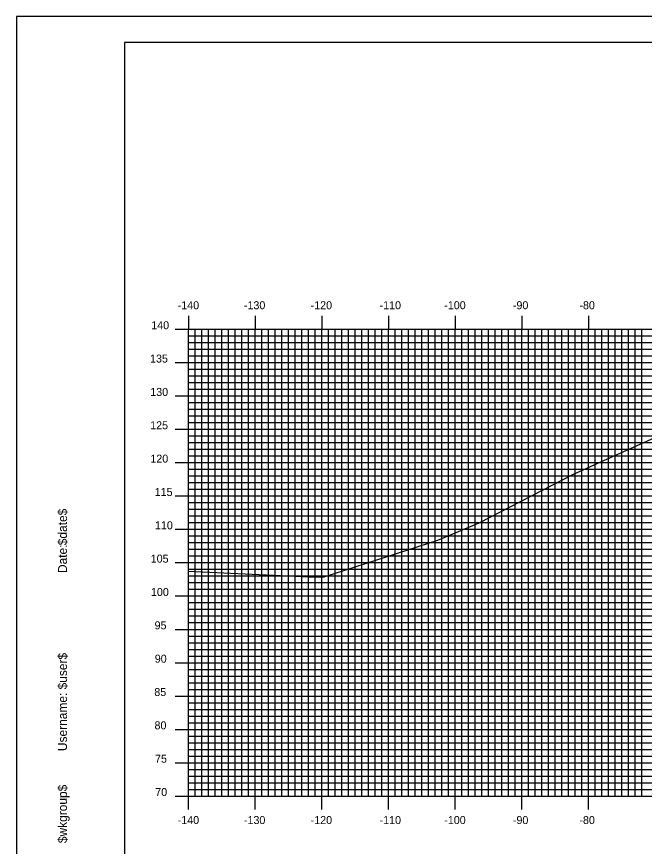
# Model space of a CAD drawing. Extents: x 859078 to 859421, y 364765 to 364985.
# Drawn here: x 859077.6 to 859171.7, y 364860.7 to 364985.2 of the extents above; entities that cross this region are included whole.
import ezdxf

# ---------------------------------------------------------------- set-up
doc = ezdxf.new("R2010")
doc.units = 0
for name, color, linetype in [('BORDER', 7, 'Continuous'), ('H_V ANNOTATION', 7, 'Continuous'), ('MAJOR', 7, 'Continuous'), ('MINOR', 7, 'Continuous'), ('PLOT BOUNDARY', 7, 'Continuous'), ('S_Roadway_Centerline', 7, 'Continuous')]:
    doc.layers.add(name, color=color, linetype=linetype)

msp = doc.modelspace()

# ---------------------------------------------------------------- linework, layer by layer
at = {"layer": 'BORDER'}
msp.add_lwpolyline([(859093.76, 364771.3), (859413.76, 364771.3), (859413.76, 364981.3), (859093.76, 364981.3)], close=True, dxfattribs=at)
at = {"layer": 'MAJOR'}
for p, q in [((859103.36, 364940.31), (859103.36, 364938.3)), ((859113.36, 364940.31), (859113.36, 364938.3)), ((859123.36, 364940.31), (859123.36, 364938.3)), ((859133.36, 364940.31), (859133.36, 364938.3)), ((859143.36, 364940.31), (859143.36, 364938.3)), ((859153.36, 364940.31), (859153.36, 364938.3)), ((859163.36, 364940.31), (859163.36, 364938.3)), ((859101.36, 364938.3), (859103.36, 364938.3)), ((859103.36, 364938.3), (859383.36, 364938.3)), ((859103.36, 364868.3), (859103.36, 364938.3)), ((859103.36, 364868.3), (859103.36, 364938.3)), ((859103.36, 364938.3), (859383.36, 364938.3)), ((859113.36, 364868.3), (859113.36, 364938.3)), ((859123.36, 364868.3), (859123.36, 364938.3)), ((859133.36, 364868.3), (859133.36, 364938.3)), ((859143.36, 364868.3), (859143.36, 364938.3)), ((859153.36, 364868.3), (859153.36, 364938.3)), ((859163.36, 364868.3), (859163.36, 364938.3)), ((859101.36, 364933.3), (859103.36, 364933.3)), ((859103.36, 364933.3), (859383.36, 364933.3)), ((859101.36, 364928.3), (859103.36, 364928.3)), ((859103.36, 364928.3), (859383.36, 364928.3)), ((859101.36, 364923.3), (859103.36, 364923.3)), ((859103.36, 364923.3), (859383.36, 364923.3)), ((859101.36, 364918.3), (859103.36, 364918.3)), ((859103.36, 364918.3), (859383.36, 364918.3)), ((859101.36, 364913.3), (859103.36, 364913.3)), ((859103.36, 364913.3), (859383.36, 364913.3)), ((859101.36, 364908.3), (859103.36, 364908.3)), ((859103.36, 364908.3), (859383.36, 364908.3)), ((859101.36, 364903.3), (859103.36, 364903.3)), ((859103.36, 364903.3), (859383.36, 364903.3)), ((859101.36, 364898.3), (859103.36, 364898.3)), ((859103.36, 364898.3), (859383.36, 364898.3)), ((859101.36, 364893.3), (859103.36, 364893.3)), ((859103.36, 364893.3), (859383.36, 364893.3)), ((859101.36, 364888.3), (859103.36, 364888.3)), ((859103.36, 364888.3), (859383.36, 364888.3)), ((859101.36, 364883.3), (859103.36, 364883.3)), ((859103.36, 364883.3), (859383.36, 364883.3)), ((859101.36, 364878.3), (859103.36, 364878.3)), ((859103.36, 364878.3), (859383.36, 364878.3)), ((859101.36, 364873.3), (859103.36, 364873.3)), ((859103.36, 364873.3), (859383.36, 364873.3)), ((859101.36, 364868.3), (859103.36, 364868.3)), ((859103.36, 364868.3), (859383.36, 364868.3)), ((859103.36, 364868.3), (859383.36, 364868.3)), ((859103.36, 364866.3), (859103.36, 364868.3)), ((859113.36, 364866.3), (859113.36, 364868.3)), ((859123.36, 364866.3), (859123.36, 364868.3)), ((859133.36, 364866.3), (859133.36, 364868.3)), ((859143.36, 364866.3), (859143.36, 364868.3)), ((859153.36, 364866.3), (859153.36, 364868.3)), ((859163.36, 364866.3), (859163.36, 364868.3))]:
    msp.add_line(p, q, dxfattribs=at)
at = {"layer": 'MINOR'}
for p, q in [((859103.36, 364937.3), (859383.36, 364937.3)), ((859103.36, 364937.3), (859105.36, 364937.3)), ((859104.36, 364868.3), (859104.36, 364938.3)), ((859105.36, 364868.3), (859105.36, 364938.3)), ((859106.36, 364868.3), (859106.36, 364938.3)), ((859107.36, 364868.3), (859107.36, 364938.3)), ((859108.36, 364868.3), (859108.36, 364938.3)), ((859109.36, 364868.3), (859109.36, 364938.3)), ((859110.36, 364868.3), (859110.36, 364938.3)), ((859111.36, 364868.3), (859111.36, 364938.3)), ((859112.36, 364868.3), (859112.36, 364938.3)), ((859114.36, 364868.3), (859114.36, 364938.3)), ((859115.36, 364868.3), (859115.36, 364938.3)), ((859116.36, 364868.3), (859116.36, 364938.3)), ((859117.36, 364868.3), (859117.36, 364938.3)), ((859118.36, 364868.3), (859118.36, 364938.3)), ((859119.36, 364868.3), (859119.36, 364938.3)), ((859120.36, 364868.3), (859120.36, 364938.3)), ((859121.36, 364868.3), (859121.36, 364938.3)), ((859122.36, 364868.3), (859122.36, 364938.3)), ((859124.36, 364868.3), (859124.36, 364938.3)), ((859125.36, 364868.3), (859125.36, 364938.3)), ((859126.36, 364868.3), (859126.36, 364938.3)), ((859127.36, 364868.3), (859127.36, 364938.3)), ((859128.36, 364868.3), (859128.36, 364938.3)), ((859129.36, 364868.3), (859129.36, 364938.3)), ((859130.36, 364868.3), (859130.36, 364938.3)), ((859131.36, 364868.3), (859131.36, 364938.3)), ((859132.36, 364868.3), (859132.36, 364938.3)), ((859134.36, 364868.3), (859134.36, 364938.3)), ((859135.36, 364868.3), (859135.36, 364938.3)), ((859136.36, 364868.3), (859136.36, 364938.3)), ((859137.36, 364868.3), (859137.36, 364938.3)), ((859138.36, 364868.3), (859138.36, 364938.3)), ((859139.36, 364868.3), (859139.36, 364938.3)), ((859140.36, 364868.3), (859140.36, 364938.3)), ((859141.36, 364868.3), (859141.36, 364938.3)), ((859142.36, 364868.3), (859142.36, 364938.3)), ((859144.36, 364868.3), (859144.36, 364938.3)), ((859145.36, 364868.3), (859145.36, 364938.3)), ((859146.36, 364868.3), (859146.36, 364938.3)), ((859147.36, 364868.3), (859147.36, 364938.3)), ((859148.36, 364868.3), (859148.36, 364938.3)), ((859149.36, 364868.3), (859149.36, 364938.3)), ((859150.36, 364868.3), (859150.36, 364938.3)), ((859151.36, 364868.3), (859151.36, 364938.3)), ((859152.36, 364868.3), (859152.36, 364938.3)), ((859154.36, 364868.3), (859154.36, 364938.3)), ((859155.36, 364868.3), (859155.36, 364938.3)), ((859156.36, 364868.3), (859156.36, 364938.3)), ((859157.36, 364868.3), (859157.36, 364938.3)), ((859158.36, 364868.3), (859158.36, 364938.3)), ((859159.36, 364868.3), (859159.36, 364938.3)), ((859160.36, 364868.3), (859160.36, 364938.3)), ((859161.36, 364868.3), (859161.36, 364938.3)), ((859162.36, 364868.3), (859162.36, 364938.3)), ((859164.36, 364868.3), (859164.36, 364938.3)), ((859165.36, 364868.3), (859165.36, 364938.3)), ((859166.36, 364868.3), (859166.36, 364938.3)), ((859167.36, 364868.3), (859167.36, 364938.3)), ((859168.36, 364868.3), (859168.36, 364938.3)), ((859169.36, 364868.3), (859169.36, 364938.3)), ((859170.36, 364868.3), (859170.36, 364938.3)), ((859171.36, 364868.3), (859171.36, 364938.3)), ((859103.36, 364936.3), (859383.36, 364936.3)), ((859103.36, 364936.3), (859105.36, 364936.3)), ((859103.36, 364935.3), (859383.36, 364935.3)), ((859103.36, 364935.3), (859105.36, 364935.3)), ((859103.36, 364934.3), (859383.36, 364934.3)), ((859103.36, 364934.3), (859105.36, 364934.3)), ((859103.36, 364932.3), (859383.36, 364932.3)), ((859103.36, 364932.3), (859105.36, 364932.3)), ((859103.36, 364931.3), (859383.36, 364931.3)), ((859103.36, 364931.3), (859105.36, 364931.3)), ((859103.36, 364930.3), (859383.36, 364930.3)), ((859103.36, 364930.3), (859105.36, 364930.3)), ((859103.36, 364929.3), (859383.36, 364929.3)), ((859103.36, 364929.3), (859105.36, 364929.3)), ((859103.36, 364927.3), (859383.36, 364927.3)), ((859103.36, 364927.3), (859105.36, 364927.3)), ((859103.36, 364926.3), (859383.36, 364926.3)), ((859103.36, 364926.3), (859105.36, 364926.3)), ((859103.36, 364925.3), (859383.36, 364925.3)), ((859103.36, 364925.3), (859105.36, 364925.3)), ((859103.36, 364924.3), (859383.36, 364924.3)), ((859103.36, 364924.3), (859105.36, 364924.3)), ((859103.36, 364922.3), (859383.36, 364922.3)), ((859103.36, 364922.3), (859105.36, 364922.3)), ((859103.36, 364921.3), (859383.36, 364921.3)), ((859103.36, 364921.3), (859105.36, 364921.3)), ((859103.36, 364920.3), (859383.36, 364920.3)), ((859103.36, 364920.3), (859105.36, 364920.3)), ((859103.36, 364919.3), (859383.36, 364919.3)), ((859103.36, 364919.3), (859105.36, 364919.3)), ((859103.36, 364917.3), (859383.36, 364917.3)), ((859103.36, 364917.3), (859105.36, 364917.3)), ((859103.36, 364916.3), (859383.36, 364916.3)), ((859103.36, 364916.3), (859105.36, 364916.3)), ((859103.36, 364915.3), (859383.36, 364915.3)), ((859103.36, 364915.3), (859105.36, 364915.3)), ((859103.36, 364914.3), (859383.36, 364914.3)), ((859103.36, 364914.3), (859105.36, 364914.3)), ((859103.36, 364912.3), (859383.36, 364912.3)), ((859103.36, 364912.3), (859105.36, 364912.3)), ((859103.36, 364911.3), (859383.36, 364911.3)), ((859103.36, 364911.3), (859105.36, 364911.3)), ((859103.36, 364910.3), (859383.36, 364910.3)), ((859103.36, 364910.3), (859105.36, 364910.3)), ((859103.36, 364909.3), (859383.36, 364909.3)), ((859103.36, 364909.3), (859105.36, 364909.3)), ((859103.36, 364907.3), (859383.36, 364907.3)), ((859103.36, 364907.3), (859105.36, 364907.3)), ((859103.36, 364906.3), (859383.36, 364906.3)), ((859103.36, 364906.3), (859105.36, 364906.3)), ((859103.36, 364905.3), (859383.36, 364905.3)), ((859103.36, 364905.3), (859105.36, 364905.3)), ((859103.36, 364904.3), (859383.36, 364904.3)), ((859103.36, 364904.3), (859105.36, 364904.3)), ((859103.36, 364902.3), (859383.36, 364902.3)), ((859103.36, 364902.3), (859105.36, 364902.3)), ((859103.36, 364901.3), (859383.36, 364901.3)), ((859103.36, 364901.3), (859105.36, 364901.3)), ((859103.36, 364900.3), (859383.36, 364900.3)), ((859103.36, 364900.3), (859105.36, 364900.3)), ((859103.36, 364899.3), (859383.36, 364899.3)), ((859103.36, 364899.3), (859105.36, 364899.3)), ((859103.36, 364897.3), (859383.36, 364897.3)), ((859103.36, 364897.3), (859105.36, 364897.3)), ((859103.36, 364896.3), (859383.36, 364896.3)), ((859103.36, 364896.3), (859105.36, 364896.3)), ((859103.36, 364895.3), (859383.36, 364895.3)), ((859103.36, 364895.3), (859105.36, 364895.3)), ((859103.36, 364894.3), (859383.36, 364894.3)), ((859103.36, 364894.3), (859105.36, 364894.3)), ((859103.36, 364892.3), (859383.36, 364892.3)), ((859103.36, 364892.3), (859105.36, 364892.3)), ((859103.36, 364891.3), (859383.36, 364891.3)), ((859103.36, 364891.3), (859105.36, 364891.3)), ((859103.36, 364890.3), (859383.36, 364890.3)), ((859103.36, 364890.3), (859105.36, 364890.3)), ((859103.36, 364889.3), (859383.36, 364889.3)), ((859103.36, 364889.3), (859105.36, 364889.3)), ((859103.36, 364887.3), (859383.36, 364887.3)), ((859103.36, 364887.3), (859105.36, 364887.3)), ((859103.36, 364886.3), (859383.36, 364886.3)), ((859103.36, 364886.3), (859105.36, 364886.3)), ((859103.36, 364885.3), (859383.36, 364885.3)), ((859103.36, 364885.3), (859105.36, 364885.3)), ((859103.36, 364884.3), (859383.36, 364884.3)), ((859103.36, 364884.3), (859105.36, 364884.3)), ((859103.36, 364882.3), (859383.36, 364882.3)), ((859103.36, 364882.3), (859105.36, 364882.3)), ((859103.36, 364881.3), (859383.36, 364881.3)), ((859103.36, 364881.3), (859105.36, 364881.3)), ((859103.36, 364880.3), (859383.36, 364880.3)), ((859103.36, 364880.3), (859105.36, 364880.3)), ((859103.36, 364879.3), (859383.36, 364879.3)), ((859103.36, 364879.3), (859105.36, 364879.3)), ((859103.36, 364877.3), (859383.36, 364877.3)), ((859103.36, 364877.3), (859105.36, 364877.3)), ((859103.36, 364876.3), (859383.36, 364876.3)), ((859103.36, 364876.3), (859105.36, 364876.3)), ((859103.36, 364875.3), (859383.36, 364875.3)), ((859103.36, 364875.3), (859105.36, 364875.3)), ((859103.36, 364874.3), (859383.36, 364874.3)), ((859103.36, 364874.3), (859105.36, 364874.3)), ((859103.36, 364872.3), (859383.36, 364872.3)), ((859103.36, 364872.3), (859105.36, 364872.3)), ((859103.36, 364871.3), (859383.36, 364871.3)), ((859103.36, 364871.3), (859105.36, 364871.3)), ((859103.36, 364870.3), (859383.36, 364870.3)), ((859103.36, 364870.3), (859105.36, 364870.3)), ((859103.36, 364869.3), (859383.36, 364869.3)), ((859103.36, 364869.3), (859105.36, 364869.3))]:
    msp.add_line(p, q, dxfattribs=at)
at = {"layer": 'PLOT BOUNDARY'}
msp.add_lwpolyline([(859077.57, 364765.18), (859417.57, 364765.18), (859417.57, 364985.18), (859077.57, 364985.18)], close=True, dxfattribs=at)
at = {"layer": 'S_Roadway_Centerline'}
msp.add_lwpolyline([(859103.36, 364902.01), (859121.41, 364901.16), (859123.7, 364901.17), (859140.77, 364906.69), (859146.96, 364909.28), (859161.1, 364916.57), (859177.76, 364924.08), (859181.57, 364925.69), (859191.17, 364926.32), (859200.46, 364926.88), (859206.7, 364927.09), (859232.95, 364927.94), (859237.94, 364928.01), (859251.9, 364928.18), (859265.53, 364922.58), (859267.32, 364921.76), (859278.31, 364916.2)], dxfattribs=at)

# ---------------------------------------------------------------- texts
at = {"layer": 'BORDER'}
for s, p in [('$date$', (859085.13, 364905.91)), ('Date:', (859085.13, 364901.74)), ('$user$', (859085.13, 364884.29)), ('Username:', (859085.13, 364875.04)), ('$wkgroup$', (859085.13, 364861.24))]:
    msp.add_text(s, height=1.339, rotation=90, dxfattribs=at).set_placement(p)
at = {"layer": 'H_V ANNOTATION'}
for s, p in [('-140', (859101.74, 364941.3)), ('-130', (859111.67, 364941.3)), ('-120', (859121.68, 364941.3)), ('-110', (859132.02, 364941.3)), ('-100', (859141.72, 364941.3)), ('-90', (859152.01, 364941.3)), ('-80', (859161.99, 364941.3)), ('140', (859097.77, 364938.3)), ('135', (859097.59, 364933.3)), ('130', (859097.62, 364928.3)), ('125', (859097.61, 364923.3)), ('120', (859097.64, 364918.3)), ('115', (859098.29, 364913.3)), ('110', (859098.33, 364908.3)), ('105', (859097.69, 364903.3)), ('100', (859097.73, 364898.3)), ('95', (859098.27, 364893.3)), ('90', (859098.3, 364888.3)), ('85', (859098.23, 364883.3)), ('80', (859098.26, 364878.3)), ('75', (859098.34, 364873.3)), ('70', (859098.37, 364868.3)), ('-140', (859101.74, 364864.1)), ('-130', (859111.67, 364864.1)), ('-120', (859121.68, 364864.1)), ('-110', (859132.02, 364864.1)), ('-100', (859141.72, 364864.1)), ('-90', (859152.01, 364864.1)), ('-80', (859161.99, 364864.1))]:
    msp.add_text(s, height=1.2, dxfattribs=at).set_placement(p)
at = {"layer": 'MAJOR'}
msp.add_text('-', height=0.012, dxfattribs=at).set_placement((859103.35, 364868.3))

doc.saveas('drawing.dxf')
